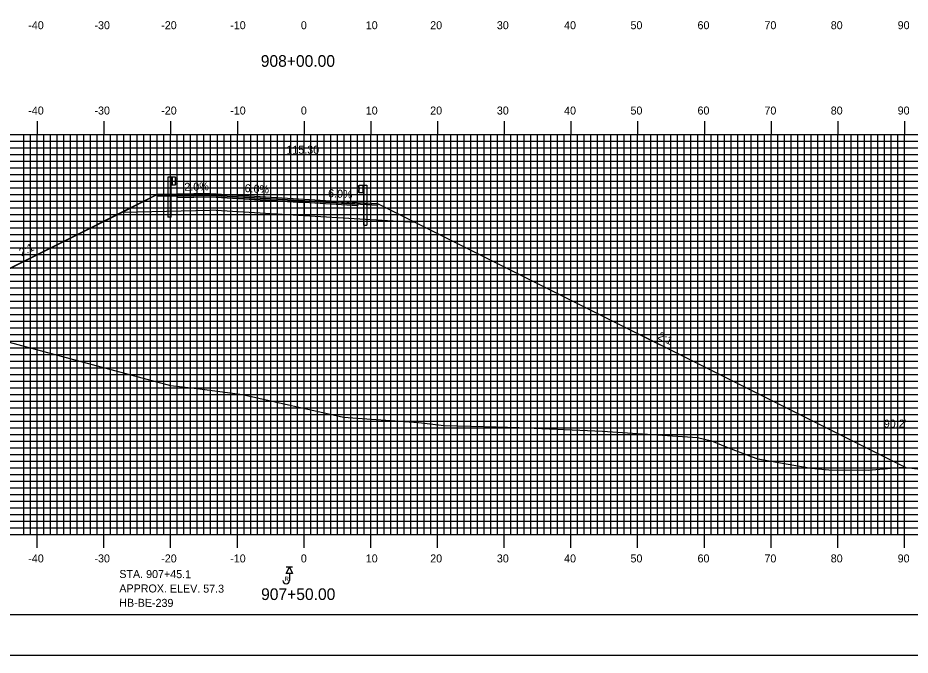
# Model space of a CAD drawing. Extents: x 858291 to 858634, y 364765 to 364985.
# Drawn here: x 858413.4 to 858547.2, y 364765.2 to 364860.8 of the extents above; entities that cross this region are included whole.
import ezdxf

# ---------------------------------------------------------------- set-up
doc = ezdxf.new("R2010")
doc.units = 0
for name, color, linetype in [('ANNOTATION', 7, 'Continuous'), ('BORDER', 7, 'Continuous'), ('BORING - REFUSAL', 7, 'Continuous'), ('D_Guardrail_Beam_Lt', 7, 'Continuous'), ('D_Guardrail_Beam_Rt', 7, 'Continuous'), ('D_Roadway_Centerline', 7, 'Continuous'), ('D_Roadway_Centerline_Text', 7, 'Continuous'), ('D_Roadway_Edge_Shoulder', 7, 'Continuous'), ('D_Roadway_Edge_TW', 7, 'Continuous'), ('D_Roadway_Pavement', 7, 'Continuous'), ('D_Roadway_SlopeLines', 7, 'Continuous'), ('D_Roadway_SubGrade', 7, 'Continuous'), ('D_Text_Standard', 7, 'Continuous'), ('H_V ANNOTATION', 7, 'Continuous'), ('MAJOR', 7, 'Continuous'), ('MINOR', 7, 'Continuous'), ('PLOT BOUNDARY', 7, 'Continuous'), ('S_Roadway_Centerline', 7, 'Continuous')]:
    doc.layers.add(name, color=color, linetype=linetype)

msp = doc.modelspace()

# ---------------------------------------------------------------- linework, layer by layer
at = {"layer": 'BORDER'}
msp.add_lwpolyline([(858306.73, 364771.3), (858626.73, 364771.3), (858626.73, 364981.3), (858306.73, 364981.3)], close=True, dxfattribs=at)
at = {"layer": 'BORING - REFUSAL'}
for p, q in [((858454.61, 364778.38), (858453.65, 364778.38)), ((858454.13, 364777.42), (858454.13, 364776.37))]:
    msp.add_line(p, q, dxfattribs=at)
msp.add_lwpolyline([(858454.13, 364778.38), (858454.61, 364777.42), (858453.65, 364777.42)], close=True, dxfattribs=at)
msp.add_arc((858453.65, 364776.37), 0.485, 180, 0, dxfattribs=at)
at = {"layer": 'D_Guardrail_Beam_Lt'}
for p, q in [((858435.9, 364836.92), (858435.9, 364830.92)), ((858436.38, 364836.92), (858435.9, 364836.92)), ((858437.06, 364836.92), (858436.38, 364836.92)), ((858436.38, 364836.92), (858436.38, 364835.76)), ((858436.44, 364836.92), (858436.44, 364835.76)), ((858436.54, 364836.92), (858436.54, 364835.76)), ((858437.06, 364835.76), (858437.06, 364836.92)), ((858437.06, 364836.84), (858437.14, 364836.82)), ((858437.07, 364836.37), (858437.07, 364836.3)), ((858437.3, 364836.57), (858437.1, 364836.44)), ((858437.1, 364836.24), (858437.3, 364836.1)), ((858437.15, 364836.82), (858437.3, 364836.72)), ((858436.38, 364835.76), (858437.06, 364835.76)), ((858436.4, 364830.92), (858436.4, 364835.76)), ((858437.14, 364835.85), (858437.06, 364835.84)), ((858437.3, 364835.96), (858437.15, 364835.86)), ((858436.4, 364830.92), (858435.9, 364830.92))]:
    msp.add_line(p, q, dxfattribs=at)
for centre, major_axis, start_param, end_param in [((858437.15, 364836.37), (-0.0789, 0), 5.323254, 6.283185), ((858437.15, 364836.3), (-0.0789, 0), 6.283185, 7.243116), ((858437.13, 364836.78), (0.0417, 0), 0.959931, 1.376053), ((858437.25, 364836.65), (0.0877, 0), 5.323254, 7.243116), ((858437.13, 364835.89), (0.0417, 0), 4.907132, 5.323254), ((858437.25, 364836.03), (0.0877, 0), 5.323254, 7.243116)]:
    msp.add_ellipse(centre, major_axis=major_axis, ratio=0.995501, start_param=start_param, end_param=end_param, dxfattribs=at)
at = {"layer": 'D_Guardrail_Beam_Rt'}
for p, q in [((858464.51, 364835.6), (858464.37, 364835.5)), ((858464.37, 364835.35), (858464.57, 364835.22)), ((858464.57, 364835.02), (858464.37, 364834.88)), ((858464.6, 364835.62), (858464.53, 364835.6)), ((858464.6, 364835.7), (858465.29, 364835.7)), ((858464.6, 364834.54), (858464.6, 364835.7)), ((858464.6, 364835.15), (858464.6, 364835.08)), ((858465.13, 364835.7), (858465.13, 364834.54)), ((858465.23, 364835.7), (858465.23, 364834.54)), ((858465.29, 364835.7), (858465.76, 364835.7)), ((858465.29, 364835.7), (858465.29, 364834.54)), ((858465.76, 364835.7), (858465.76, 364829.7)), ((858464.37, 364834.74), (858464.51, 364834.64)), ((858464.53, 364834.63), (858464.6, 364834.62)), ((858465.29, 364834.54), (858464.6, 364834.54)), ((858465.27, 364829.7), (858465.27, 364834.54)), ((858465.27, 364829.7), (858465.76, 364829.7))]:
    msp.add_line(p, q, dxfattribs=at)
for centre, major_axis, start_param, end_param in [((858464.42, 364835.43), (-0.0877, 0), 5.323254, 7.243116), ((858464.42, 364834.81), (-0.0877, 0), 5.323254, 7.243116), ((858464.54, 364835.56), (-0.0417, 0), 4.907132, 5.323254), ((858464.52, 364835.15), (0.0789, 0), 0, 0.959931), ((858464.52, 364835.08), (0.0789, 0), 5.323254, 6.283185), ((858464.54, 364834.67), (-0.0417, 0), 0.959931, 1.376053)]:
    msp.add_ellipse(centre, major_axis=major_axis, ratio=0.995501, start_param=start_param, end_param=end_param, dxfattribs=at)
at = {"layer": 'D_Roadway_Centerline'}
msp.add_lwpolyline([(858397.71, 364815.96), (858429.13, 364831.67), (858434.33, 364834.28), (858437.33, 364834.34), (858442.33, 364834.44), (858456.33, 364833.6), (858464.33, 364833.12), (858467.33, 364832.94), (858473.02, 364830.1), (858546.52, 364793.34)], dxfattribs=at)
at = {"layer": 'D_Roadway_Edge_Shoulder'}
for points in [[(858442.33, 364834.44), (858437.33, 364834.34), (858437.33, 364834.34), (858434.33, 364834.28), (858434.33, 364834.03), (858437.33, 364834.09), (858442.33, 364834.19)], [(858456.33, 364833.6), (858464.33, 364833.12), (858464.33, 364833.12), (858467.33, 364832.94), (858467.33, 364832.69), (858456.33, 364833.35)]]:
    msp.add_lwpolyline(points, close=True, dxfattribs=at)
at = {"layer": 'D_Roadway_Edge_TW'}
msp.add_lwpolyline([(858442.33, 364834.44), (858456.33, 364833.6), (858456.33, 364833.35), (858442.33, 364834.19)], close=True, dxfattribs=at)
at = {"layer": 'D_Roadway_Pavement'}
for points in [[(858442.33, 364834.19), (858437.33, 364834.09), (858437.33, 364833.84), (858442.33, 364833.94)], [(858442.33, 364834.19), (858456.33, 364833.35), (858456.33, 364833.1), (858442.33, 364833.94)]]:
    msp.add_lwpolyline(points, close=True, dxfattribs=at)
for points in [[(858456.33, 364833.35), (858456.33, 364833.1)], [(858456.33, 364833.35), (858456.33, 364833.1)], [(858456.33, 364833.35), (858456.33, 364833.1)], [(858456.33, 364833.35), (858464.33, 364832.87), (858464.33, 364832.62), (858456.33, 364833.1)]]:
    msp.add_lwpolyline(points, dxfattribs=at)
at = {"layer": 'D_Roadway_SlopeLines'}
for points in [[(858434.33, 364834.28), (858397.71, 364815.96)], [(858467.33, 364832.94), (858546.52, 364793.34)]]:
    msp.add_lwpolyline(points, dxfattribs=at)
at = {"layer": 'D_Roadway_SubGrade'}
for points in [[(858442.33, 364833.94), (858437.33, 364833.84), (858437.33, 364834.09), (858434.33, 364834.03), (858434.33, 364834.28), (858429.13, 364831.67), (858442.33, 364831.94)], [(858442.33, 364833.94), (858456.33, 364833.1), (858456.33, 364831.1), (858442.33, 364831.94)], [(858456.33, 364833.1), (858456.33, 364833.35), (858467.33, 364832.69), (858467.33, 364832.94), (858473.02, 364830.1), (858456.33, 364831.1)]]:
    msp.add_lwpolyline(points, close=True, dxfattribs=at)
at = {"layer": 'MAJOR'}
for p, q in [((858416.33, 364845.31), (858416.33, 364843.3)), ((858426.33, 364845.31), (858426.33, 364843.3)), ((858436.33, 364845.31), (858436.33, 364843.3)), ((858446.33, 364845.31), (858446.33, 364843.3)), ((858456.33, 364845.31), (858456.33, 364843.3)), ((858466.33, 364845.31), (858466.33, 364843.3)), ((858476.33, 364845.31), (858476.33, 364843.3)), ((858486.33, 364845.31), (858486.33, 364843.3)), ((858496.33, 364845.31), (858496.33, 364843.3)), ((858506.33, 364845.31), (858506.33, 364843.3)), ((858516.33, 364845.31), (858516.33, 364843.3)), ((858526.33, 364845.31), (858526.33, 364843.3)), ((858536.33, 364845.31), (858536.33, 364843.3)), ((858546.33, 364845.31), (858546.33, 364843.3)), ((858316.33, 364843.3), (858596.33, 364843.3)), ((858316.33, 364843.3), (858596.33, 364843.3)), ((858416.33, 364783.3), (858416.33, 364843.3)), ((858426.33, 364783.3), (858426.33, 364843.3)), ((858436.33, 364783.3), (858436.33, 364843.3)), ((858446.33, 364783.3), (858446.33, 364843.3)), ((858456.33, 364783.3), (858456.33, 364843.3)), ((858466.33, 364783.3), (858466.33, 364843.3)), ((858476.33, 364783.3), (858476.33, 364843.3)), ((858486.33, 364783.3), (858486.33, 364843.3)), ((858496.33, 364783.3), (858496.33, 364843.3)), ((858506.33, 364783.3), (858506.33, 364843.3)), ((858516.33, 364783.3), (858516.33, 364843.3)), ((858526.33, 364783.3), (858526.33, 364843.3)), ((858536.33, 364783.3), (858536.33, 364843.3)), ((858546.33, 364783.3), (858546.33, 364843.3)), ((858316.33, 364838.3), (858596.33, 364838.3)), ((858316.33, 364833.3), (858596.33, 364833.3)), ((858316.33, 364828.3), (858596.33, 364828.3)), ((858316.33, 364823.3), (858596.33, 364823.3)), ((858316.33, 364818.3), (858596.33, 364818.3)), ((858316.33, 364813.3), (858596.33, 364813.3)), ((858316.33, 364808.3), (858596.33, 364808.3)), ((858316.33, 364803.3), (858596.33, 364803.3)), ((858316.33, 364798.3), (858596.33, 364798.3)), ((858316.33, 364793.3), (858596.33, 364793.3)), ((858316.33, 364788.3), (858596.33, 364788.3)), ((858316.33, 364783.3), (858596.33, 364783.3)), ((858316.33, 364783.3), (858596.33, 364783.3)), ((858416.33, 364781.3), (858416.33, 364783.3)), ((858426.33, 364781.3), (858426.33, 364783.3)), ((858436.33, 364781.3), (858436.33, 364783.3)), ((858446.33, 364781.3), (858446.33, 364783.3)), ((858456.33, 364781.3), (858456.33, 364783.3)), ((858466.33, 364781.3), (858466.33, 364783.3)), ((858476.33, 364781.3), (858476.33, 364783.3)), ((858486.33, 364781.3), (858486.33, 364783.3)), ((858496.33, 364781.3), (858496.33, 364783.3)), ((858506.33, 364781.3), (858506.33, 364783.3)), ((858516.33, 364781.3), (858516.33, 364783.3)), ((858526.33, 364781.3), (858526.33, 364783.3)), ((858536.33, 364781.3), (858536.33, 364783.3)), ((858546.33, 364781.3), (858546.33, 364783.3))]:
    msp.add_line(p, q, dxfattribs=at)
at = {"layer": 'MINOR'}
for p, q in [((858414.33, 364783.3), (858414.33, 364843.3)), ((858415.33, 364783.3), (858415.33, 364843.3)), ((858417.33, 364783.3), (858417.33, 364843.3)), ((858418.33, 364783.3), (858418.33, 364843.3)), ((858419.33, 364783.3), (858419.33, 364843.3)), ((858420.33, 364783.3), (858420.33, 364843.3)), ((858421.33, 364783.3), (858421.33, 364843.3)), ((858422.33, 364783.3), (858422.33, 364843.3)), ((858423.33, 364783.3), (858423.33, 364843.3)), ((858424.33, 364783.3), (858424.33, 364843.3)), ((858425.33, 364783.3), (858425.33, 364843.3)), ((858427.33, 364783.3), (858427.33, 364843.3)), ((858428.33, 364783.3), (858428.33, 364843.3)), ((858429.33, 364783.3), (858429.33, 364843.3)), ((858430.33, 364783.3), (858430.33, 364843.3)), ((858431.33, 364783.3), (858431.33, 364843.3)), ((858432.33, 364783.3), (858432.33, 364843.3)), ((858433.33, 364783.3), (858433.33, 364843.3)), ((858434.33, 364783.3), (858434.33, 364843.3)), ((858435.33, 364783.3), (858435.33, 364843.3)), ((858437.33, 364783.3), (858437.33, 364843.3)), ((858438.33, 364783.3), (858438.33, 364843.3)), ((858439.33, 364783.3), (858439.33, 364843.3)), ((858440.33, 364783.3), (858440.33, 364843.3)), ((858441.33, 364783.3), (858441.33, 364843.3)), ((858442.33, 364783.3), (858442.33, 364843.3)), ((858443.33, 364783.3), (858443.33, 364843.3)), ((858444.33, 364783.3), (858444.33, 364843.3)), ((858445.33, 364783.3), (858445.33, 364843.3)), ((858447.33, 364783.3), (858447.33, 364843.3)), ((858448.33, 364783.3), (858448.33, 364843.3)), ((858449.33, 364783.3), (858449.33, 364843.3)), ((858450.33, 364783.3), (858450.33, 364843.3)), ((858451.33, 364783.3), (858451.33, 364843.3)), ((858452.33, 364783.3), (858452.33, 364843.3)), ((858453.33, 364783.3), (858453.33, 364843.3)), ((858454.33, 364783.3), (858454.33, 364843.3)), ((858455.33, 364783.3), (858455.33, 364843.3)), ((858457.33, 364783.3), (858457.33, 364843.3)), ((858458.33, 364783.3), (858458.33, 364843.3)), ((858459.33, 364783.3), (858459.33, 364843.3)), ((858460.33, 364783.3), (858460.33, 364843.3)), ((858461.33, 364783.3), (858461.33, 364843.3)), ((858462.33, 364783.3), (858462.33, 364843.3)), ((858463.33, 364783.3), (858463.33, 364843.3)), ((858464.33, 364783.3), (858464.33, 364843.3)), ((858465.33, 364783.3), (858465.33, 364843.3)), ((858467.33, 364783.3), (858467.33, 364843.3)), ((858468.33, 364783.3), (858468.33, 364843.3)), ((858469.33, 364783.3), (858469.33, 364843.3)), ((858470.33, 364783.3), (858470.33, 364843.3)), ((858471.33, 364783.3), (858471.33, 364843.3)), ((858472.33, 364783.3), (858472.33, 364843.3)), ((858473.33, 364783.3), (858473.33, 364843.3)), ((858474.33, 364783.3), (858474.33, 364843.3)), ((858475.33, 364783.3), (858475.33, 364843.3)), ((858477.33, 364783.3), (858477.33, 364843.3)), ((858478.33, 364783.3), (858478.33, 364843.3)), ((858479.33, 364783.3), (858479.33, 364843.3)), ((858480.33, 364783.3), (858480.33, 364843.3)), ((858481.33, 364783.3), (858481.33, 364843.3)), ((858482.33, 364783.3), (858482.33, 364843.3)), ((858483.33, 364783.3), (858483.33, 364843.3)), ((858484.33, 364783.3), (858484.33, 364843.3)), ((858485.33, 364783.3), (858485.33, 364843.3)), ((858487.33, 364783.3), (858487.33, 364843.3)), ((858488.33, 364783.3), (858488.33, 364843.3)), ((858489.33, 364783.3), (858489.33, 364843.3)), ((858490.33, 364783.3), (858490.33, 364843.3)), ((858491.33, 364783.3), (858491.33, 364843.3)), ((858492.33, 364783.3), (858492.33, 364843.3)), ((858493.33, 364783.3), (858493.33, 364843.3)), ((858494.33, 364783.3), (858494.33, 364843.3)), ((858495.33, 364783.3), (858495.33, 364843.3)), ((858497.33, 364783.3), (858497.33, 364843.3)), ((858498.33, 364783.3), (858498.33, 364843.3)), ((858499.33, 364783.3), (858499.33, 364843.3)), ((858500.33, 364783.3), (858500.33, 364843.3)), ((858501.33, 364783.3), (858501.33, 364843.3)), ((858502.33, 364783.3), (858502.33, 364843.3)), ((858503.33, 364783.3), (858503.33, 364843.3)), ((858504.33, 364783.3), (858504.33, 364843.3)), ((858505.33, 364783.3), (858505.33, 364843.3)), ((858507.33, 364783.3), (858507.33, 364843.3)), ((858508.33, 364783.3), (858508.33, 364843.3)), ((858509.33, 364783.3), (858509.33, 364843.3)), ((858510.33, 364783.3), (858510.33, 364843.3)), ((858511.33, 364783.3), (858511.33, 364843.3)), ((858512.33, 364783.3), (858512.33, 364843.3)), ((858513.33, 364783.3), (858513.33, 364843.3)), ((858514.33, 364783.3), (858514.33, 364843.3)), ((858515.33, 364783.3), (858515.33, 364843.3)), ((858517.33, 364783.3), (858517.33, 364843.3)), ((858518.33, 364783.3), (858518.33, 364843.3)), ((858519.33, 364783.3), (858519.33, 364843.3)), ((858520.33, 364783.3), (858520.33, 364843.3)), ((858521.33, 364783.3), (858521.33, 364843.3)), ((858522.33, 364783.3), (858522.33, 364843.3)), ((858523.33, 364783.3), (858523.33, 364843.3)), ((858524.33, 364783.3), (858524.33, 364843.3)), ((858525.33, 364783.3), (858525.33, 364843.3)), ((858527.33, 364783.3), (858527.33, 364843.3)), ((858528.33, 364783.3), (858528.33, 364843.3)), ((858529.33, 364783.3), (858529.33, 364843.3)), ((858530.33, 364783.3), (858530.33, 364843.3)), ((858531.33, 364783.3), (858531.33, 364843.3)), ((858532.33, 364783.3), (858532.33, 364843.3)), ((858533.33, 364783.3), (858533.33, 364843.3)), ((858534.33, 364783.3), (858534.33, 364843.3)), ((858535.33, 364783.3), (858535.33, 364843.3)), ((858537.33, 364783.3), (858537.33, 364843.3)), ((858538.33, 364783.3), (858538.33, 364843.3)), ((858539.33, 364783.3), (858539.33, 364843.3)), ((858540.33, 364783.3), (858540.33, 364843.3)), ((858541.33, 364783.3), (858541.33, 364843.3)), ((858542.33, 364783.3), (858542.33, 364843.3)), ((858543.33, 364783.3), (858543.33, 364843.3)), ((858544.33, 364783.3), (858544.33, 364843.3)), ((858545.33, 364783.3), (858545.33, 364843.3)), ((858316.33, 364842.3), (858596.33, 364842.3)), ((858316.33, 364841.3), (858596.33, 364841.3)), ((858316.33, 364840.3), (858596.33, 364840.3)), ((858316.33, 364839.3), (858596.33, 364839.3)), ((858316.33, 364837.3), (858596.33, 364837.3)), ((858316.33, 364836.3), (858596.33, 364836.3)), ((858316.33, 364835.3), (858596.33, 364835.3)), ((858316.33, 364834.3), (858596.33, 364834.3)), ((858316.33, 364832.3), (858596.33, 364832.3)), ((858316.33, 364831.3), (858596.33, 364831.3)), ((858316.33, 364830.3), (858596.33, 364830.3)), ((858316.33, 364829.3), (858596.33, 364829.3)), ((858316.33, 364827.3), (858596.33, 364827.3)), ((858316.33, 364826.3), (858596.33, 364826.3)), ((858316.33, 364825.3), (858596.33, 364825.3)), ((858316.33, 364824.3), (858596.33, 364824.3)), ((858316.33, 364822.3), (858596.33, 364822.3)), ((858316.33, 364821.3), (858596.33, 364821.3)), ((858316.33, 364820.3), (858596.33, 364820.3)), ((858316.33, 364819.3), (858596.33, 364819.3)), ((858316.33, 364817.3), (858596.33, 364817.3)), ((858316.33, 364816.3), (858596.33, 364816.3)), ((858316.33, 364815.3), (858596.33, 364815.3)), ((858316.33, 364814.3), (858596.33, 364814.3)), ((858316.33, 364812.3), (858596.33, 364812.3)), ((858316.33, 364811.3), (858596.33, 364811.3)), ((858316.33, 364810.3), (858596.33, 364810.3)), ((858316.33, 364809.3), (858596.33, 364809.3)), ((858316.33, 364807.3), (858596.33, 364807.3)), ((858316.33, 364806.3), (858596.33, 364806.3)), ((858316.33, 364805.3), (858596.33, 364805.3)), ((858316.33, 364804.3), (858596.33, 364804.3)), ((858316.33, 364802.3), (858596.33, 364802.3)), ((858316.33, 364801.3), (858596.33, 364801.3)), ((858316.33, 364800.3), (858596.33, 364800.3)), ((858316.33, 364799.3), (858596.33, 364799.3)), ((858316.33, 364797.3), (858596.33, 364797.3)), ((858316.33, 364796.3), (858596.33, 364796.3)), ((858316.33, 364795.3), (858596.33, 364795.3)), ((858316.33, 364794.3), (858596.33, 364794.3)), ((858316.33, 364792.3), (858596.33, 364792.3)), ((858316.33, 364791.3), (858596.33, 364791.3)), ((858316.33, 364790.3), (858596.33, 364790.3)), ((858316.33, 364789.3), (858596.33, 364789.3)), ((858316.33, 364787.3), (858596.33, 364787.3)), ((858316.33, 364786.3), (858596.33, 364786.3)), ((858316.33, 364785.3), (858596.33, 364785.3)), ((858316.33, 364784.3), (858596.33, 364784.3))]:
    msp.add_line(p, q, dxfattribs=at)
at = {"layer": 'PLOT BOUNDARY'}
msp.add_lwpolyline([(858290.55, 364765.18), (858630.55, 364765.18), (858630.55, 364985.18), (858290.55, 364985.18)], close=True, dxfattribs=at)
at = {"layer": 'S_Roadway_Centerline'}
msp.add_lwpolyline([(858408.18, 364813.22), (858422.53, 364809.35), (858436.31, 364805.63), (858440.29, 364805.18), (858447.1, 364804.27), (858462.26, 364800.91), (858473.46, 364800.1), (858477.31, 364799.66), (858483.4, 364799.47), (858488.55, 364799.35), (858501.07, 364798.78), (858515.31, 364797.85), (858517.38, 364797.36), (858519.72, 364796.4), (858523.33, 364794.99), (858524.34, 364794.65), (858528.91, 364793.86), (858532.34, 364793.26), (858535, 364793.01), (858540.89, 364792.95), (858546.11, 364793.39), (858551.3, 364792.79)], dxfattribs=at)

# ---------------------------------------------------------------- texts
at = {"layer": 'ANNOTATION'}
for s, rotation, p in [('2.0%', 1.1458, (858438.4, 364834.85)), ('6.0%', 356.5664, (858447.4, 364834.67)), ('6.0%', 356.5664, (858459.9, 364833.92)), ('2:1', 26.5651, (858413.98, 364824.98)), ('2:1', 333.3359, (858509.21, 364812.7))]:
    msp.add_text(s, height=1.2, rotation=rotation, dxfattribs=at).set_placement(p)
at = {"layer": 'BORING - REFUSAL'}
for s, p in [('STA. 907+45.1', (858428.64, 364776.77)), ('APPROX. ELEV. 57.3', (858428.64, 364774.61)), ('HB-BE-239', (858428.63, 364772.45))]:
    msp.add_text(s, height=1.2, rotation=359.8142, dxfattribs=at).set_placement(p)
msp.add_text('R', height=0.64, dxfattribs=at).set_placement((858453.42, 364776.31))
at = {"layer": 'D_Roadway_Centerline_Text'}
msp.add_text('115.30', height=1.2, dxfattribs=at).set_placement((858453.68, 364840.42))
at = {"layer": 'D_Text_Standard'}
msp.add_text("90.2'", height=1.2, dxfattribs=at).set_placement((858543.23, 364799.32))
at = {"layer": 'H_V ANNOTATION'}
for s, height, p in [('-40', 1.2, (858414.99, 364859.1)), ('-30', 1.2, (858424.91, 364859.1)), ('-20', 1.2, (858434.92, 364859.1)), ('-10', 1.2, (858445.26, 364859.1)), ('0', 1.2, (858455.85, 364859.1)), ('10', 1.2, (858465.58, 364859.1)), ('20', 1.2, (858475.24, 364859.1)), ('30', 1.2, (858485.23, 364859.1)), ('40', 1.2, (858495.31, 364859.1)), ('50', 1.2, (858505.26, 364859.1)), ('60', 1.2, (858515.31, 364859.1)), ('70', 1.2, (858525.34, 364859.1)), ('80', 1.2, (858535.28, 364859.1)), ('90', 1.2, (858545.31, 364859.1)), ('908+00.00', 1.75, (858449.84, 364853.46)), ('-40', 1.2, (858414.99, 364846.3)), ('-30', 1.2, (858424.91, 364846.3)), ('-20', 1.2, (858434.92, 364846.3)), ('-10', 1.2, (858445.26, 364846.3)), ('0', 1.2, (858455.85, 364846.3)), ('10', 1.2, (858465.58, 364846.3)), ('20', 1.2, (858475.24, 364846.3)), ('30', 1.2, (858485.23, 364846.3)), ('40', 1.2, (858495.31, 364846.3)), ('50', 1.2, (858505.26, 364846.3)), ('60', 1.2, (858515.31, 364846.3)), ('70', 1.2, (858525.34, 364846.3)), ('80', 1.2, (858535.28, 364846.3)), ('90', 1.2, (858545.31, 364846.3)), ('-40', 1.2, (858414.99, 364779.1)), ('-30', 1.2, (858424.91, 364779.1)), ('-20', 1.2, (858434.92, 364779.1)), ('-10', 1.2, (858445.26, 364779.1)), ('0', 1.2, (858455.85, 364779.1)), ('10', 1.2, (858465.58, 364779.1)), ('20', 1.2, (858475.24, 364779.1)), ('30', 1.2, (858485.23, 364779.1)), ('40', 1.2, (858495.31, 364779.1)), ('50', 1.2, (858505.26, 364779.1)), ('60', 1.2, (858515.31, 364779.1)), ('70', 1.2, (858525.34, 364779.1)), ('80', 1.2, (858535.28, 364779.1)), ('90', 1.2, (858545.31, 364779.1)), ('907+50.00', 1.75, (858449.89, 364773.46))]:
    msp.add_text(s, height=height, dxfattribs=at).set_placement(p)

doc.saveas('drawing.dxf')
